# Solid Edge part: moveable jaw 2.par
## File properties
Accuracy: 0.990
Author: CADSoft
Template: Normal.par
Last saved by: Rajat Kamboj
Revision: 7
Application: Solid Edge
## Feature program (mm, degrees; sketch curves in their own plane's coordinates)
sketch for "unnamed Protrusion 1" plane through (0, 0, 0) normal (0, -1, 0) x-axis (1, 0, 0)
  line (2.077, -7.5) -> (2.077, 52.5)
  line (2.077, 52.5) -> (-32.423, 52.5)
  line (-32.423, 52.5) -> (-32.423, -7.5)
  line (-28.923, -7.5) -> (-32.423, -7.5)
  line (-28.923, -5) -> (-28.923, -7.5)
  line (-28.923, -5) -> (-26.423, -5)
  line (-26.423, -5) -> (-26.423, -2.5)
  line (-26.423, -2.5) -> (-23.923, -2.5)
  line (-23.923, -2.5) -> (-23.923, 0)
  line (-23.923, 0) -> (-21.423, 0)
  line (-21.423, 0) -> (-21.423, 2.5)
  line (-21.423, 2.5) -> (-18.923, 2.5)
  line (-18.923, 2.5) -> (-18.923, 5)
  line (-18.923, 5) -> (-16.423, 5)
  line (-16.423, 5) -> (-16.423, 7.5)
  line (-16.423, 7.5) -> (-15.173, 7.5)
  line (-13.923, 7.5) -> (-15.173, 7.5)
  line (-13.923, 5) -> (-13.923, 7.5)
  line (-11.423, 5) -> (-13.923, 5)
  line (-11.423, 2.5) -> (-11.423, 5)
  line (-8.923, 2.5) -> (-11.423, 2.5)
  line (-8.923, 0) -> (-8.923, 2.5)
  line (-6.423, 0) -> (-8.923, 0)
  line (-6.423, -2.5) -> (-6.423, 0)
  line (-3.923, -2.5) -> (-6.423, -2.5)
  line (-3.923, -5) -> (-3.923, -2.5)
  line (-1.423, -5) -> (-3.923, -5)
  line (-1.423, -5) -> (-1.423, -7.5)
  line (-1.423, -7.5) -> (2.077, -7.5)
extrude "unnamed Protrusion 1" add finite 18 symmetric
sketch for "Hole_1" plane through (-15.173, 0, 52.5) normal (0, 0, 1) x-axis (-1, 0, 0)
  hole centre (0, 0) bore radius 6
hole "Hole_1" diameter 12 finite  VBottomAngle = 120 deg
sketch for "Hole_2" plane through (2.077, 0, 22.5) normal (1, 0, 0) x-axis (0, 1, 0)
  hole centre (0, 23) bore radius 3
hole "Hole_2" diameter 6 through
chamfer "Chamfer_2" setback 2
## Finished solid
Body 1: solid body, 38 faces, 98 edges, 60 vertices.
  Faces by surface: plane 34, cylinder 3, cone 1
  Edges by curve: line 92, circle 4, intersection 2
Bounding box of the edges (mm): 34.500 x 18.000 x 60.000, from (-32.423, -9, -7.5) to (2.077, 9, 52.5).
Cylindrical faces by radius (mm): R3 x2, R6 x1
Conical faces (half-angle, radius in mm at the cone's reference point): 60 deg R6 x1
Planar faces by outward normal: +x 7, +y 1, +z 1, -x 7, -y 1, -z 13, oblique 4
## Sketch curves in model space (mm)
line (-26.423, 0, -5) -> (-26.423, 0, -2.5)
line (-26.423, 0, -2.5) -> (-23.923, 0, -2.5)
line (-23.923, 0, -2.5) -> (-23.923, 0, 0)
line (-23.923, 0, 0) -> (-21.423, 0, 0)
line (-21.423, 0, 0) -> (-21.423, 0, 2.5)
line (-21.423, 0, 2.5) -> (-18.923, 0, 2.5)
line (-18.923, 0, 2.5) -> (-18.923, 0, 5)
line (-18.923, 0, 5) -> (-16.423, 0, 5)
line (-16.423, 0, 5) -> (-16.423, 0, 7.5)
line (-16.423, 0, 7.5) -> (-15.173, 0, 7.5)
line (-13.923, 0, 7.5) -> (-15.173, 0, 7.5)
line (-13.923, 0, 5) -> (-13.923, 0, 7.5)
line (-11.423, 0, 5) -> (-13.923, 0, 5)
line (-11.423, 0, 2.5) -> (-11.423, 0, 5)
line (-8.923, 0, 2.5) -> (-11.423, 0, 2.5)
line (-8.923, 0, 0) -> (-8.923, 0, 2.5)
line (-6.423, 0, 0) -> (-8.923, 0, 0)
line (-6.423, 0, -2.5) -> (-6.423, 0, 0)
line (-3.923, 0, -2.5) -> (-6.423, 0, -2.5)
line (-3.923, 0, -5) -> (-3.923, 0, -2.5)
line (-1.423, 0, -5) -> (-3.923, 0, -5)
line (-1.423, 0, -5) -> (-1.423, 0, -7.5)
line (-1.423, 0, -7.5) -> (2.077, 0, -7.5)
line (2.077, 0, -7.5) -> (2.077, 0, 52.5)
line (2.077, 0, 52.5) -> (-32.423, 0, 52.5)
line (-32.423, 0, 52.5) -> (-32.423, 0, -7.5)
line (-28.923, 0, -7.5) -> (-32.423, 0, -7.5)
line (-28.923, 0, -5) -> (-28.923, 0, -7.5)
line (-28.923, 0, -5) -> (-26.423, 0, -5)
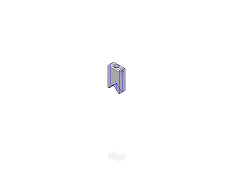
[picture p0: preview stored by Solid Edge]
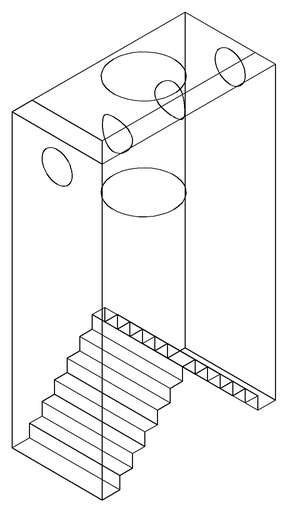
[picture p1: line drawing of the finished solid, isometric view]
